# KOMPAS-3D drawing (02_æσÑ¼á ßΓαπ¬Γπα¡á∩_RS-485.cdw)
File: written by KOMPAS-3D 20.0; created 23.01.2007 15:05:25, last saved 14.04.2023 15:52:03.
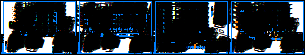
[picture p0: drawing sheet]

Sheets 1-4: A2, landscape

Document properties: Разработал: Антошин; Проверил: Тарасов; Утвердил: Шмончев; Н. контр.: Силаков; Форматы листов документа: 4xA2; Полное имя файла: \\s-tech\depts\Отдел_ПКО\Проекты\Типовые проекты МКД 2023\!Типовой проект\1_Типовой проект МКД_RS-485\02_Схема структурная_RS-485.cdw

Title block, sheet 1: Наименование: ВЛСТ 858.00.001 С3; designation: ВЛСТ 1277.01.000 С3; sheet number: 1; Количество листов документа: 8; organisation: АО ГК / "Системы и Технологии"; Форматы листов документа: A2; stored path: Y:\Проекты\ЭнергоКурган\Типовой проект\02_Рабочая док. общ\Е1_001_Сх деления.cdw; cell 302: Система учета электроэнергии (с организацией удаленного / сбора данных) потребителей; cell 303: Типовой проект ИСУЭ многоквартирного / дома с использованием проводного / канала связи RS-485; cell 304: Схема структурная АИИС; cell 320: Р
Title block, sheet 2: sheet number: 2; Форматы листов документа: A3; stored path: \\fs1.s-tech.ru\depts\Отдел_ПКО\Проекты\ГУП СК Ставрополькоммунэлектро\2021\Типовой проект\02_Рабочая документация\+С3_001_Структ_Многоквартирный дом УСПД.cdw
Title block, sheet 3: sheet number: 3
Title block, sheet 4: sheet number: 4; stored path: \\s-tech\depts\Отдел_ПКО\Проекты\Типовые проекты МКД 2023\!Типовой проект\1_Типовой проект МКД_RS-485\_Схема структурная_RS-485.cdw; designation, second copy: ВЛСТ 1277.01.000 С3-

Referenced files in \\Helios\отдел_пко\Общая папка Компас\_Addons\Signatures\: Signatures.lfr|Тарасов, Signatures.lfr, Signatures.lfr|Силаков, Signatures.lfr|Шмончев
Referenced files in C:\Program Files\ASCON\KOMPAS-3D V13\Libs\_Addons\Signatures\: Signatures.lfr
Referenced files: qlkzkl.frw, eiczbt.frw, hsklda.frw
Referenced files in C:\Program Files\ASCON\KOMPAS-3D v20\Sys\: Lighting.lts
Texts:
  Тарасов
  Силаков
  Шмончев
  Лит-Масса-Масштаб
  Материал-Предприятие
  Normal
  TXT
  Centerline
  Outline
  Этаж 2
  Этаж 1
  ВРУ №1
  Сч. ОДПУ
  Сч. МОП
  Шкаф УСПД
  УСПД
  SM-160
  Коммутатор
  Преобразователь
  Ethernet/RS-485
  RS-485
  Сч. Кв.1
  Сч. Кв.6
  Этаж 6
  ПРК
  АРК
  Электрощитовая №1
  Подвал
  Этаж 7
  Этаж 12
  Этаж 13
  Этаж 17
  Этаж 18
  Стояк СС
  Подъезд 1
  Подъезд 2
  Подъезд 3
  Подъезд N
  Электрощитовая №2
  Тех. этаж
  Вариант 3. Многоквартирный дом с этажностью - 14-18
  Щит со счетчиками на площадке этажа, активная разветвительная коробка RS-485
  GSM
  Осн. канал
  Сервер ИСУЭ
  Антенна GSM
  ВОЛС
  Оборудование
  связи
  Альт. канал
  (при необходимости)
  ВРУ №2
  ПЭФ
  Этаж 5
  Этаж 10
  Этаж 15
  ВРУ
  Сч. Кв.2
  Вариант 2. Многоквартирный дом с этажностью - 9
  Два щита со счетчиками на площадке этажа, пассивная разветвительная коробка RS-485
  Этаж 3
  Этаж 9
  Сч. Кв.3
  Сч. Кв.4
  Вариант 1. Многоквартирный дом с этажностью - до 5
  Этаж 4
  ВВГнг(А)-LS 3х2.5
  - коммутатор PLANET ISW-800T;
  интерфейса RS-485 для МКД до 18 этажей без применения АРК.
  МОП, ИПУ может изменяться.
  через ПРК ранво 30 шт. При подключении более 30 счетчиков произвести смену пары (жилы кабеля)
  магистральной линии интерфейса RS-485 (см. схема внешних проводок ВЛСТ 1277.01.002 С5).
  фаз ПЭФ-301.
  линий RS-485.
  - интеллектуальный контроллер SM160-02М/xД,
  где х - максимальное количество счетчиков (100, 150,
  - автоматический выключатель;
  Перечень сокращений
  АВ - автоматический выключатель;
  БП - блок питания;
  ВРУ - вводное распределительное устройство;
  МКД - многоквартирный дом;
  МОП -  места общего пользования;
  ОДПУ - общедомовой прибор учета;
  ПРК - пассивная разветвительная коробка;
  ПЭФ - универсальный автоматический электронный
  ИСУЭ - интеллектуальня система учета электроэнергии.
  - ПРК;
  См.ТТ п.3
  интерфейса RS-485 для МКД до 9 этажей без применения АРК.
  может изменяться.
  изменяться .
  RS-485 для МКД до 5 этажей.
  ИПУ может изменяться.
  ПЭФ-301.
  - однофазный счетчик КВАНТ ST1000-9;
  - трехфазный счетчик КВАНТ ST2000-12;
  АРК - активная разветвительная коробка;
  ПЛ - преобразователь линии;
  - АРК;
  FTP4-4х2х0,51
  - кабель FTP4-4х2х0,51.
  RS-485 для МКД до 18 этажей с применением АРК.
  Вариант 4. Многоквартирный дом с этажностью - 14-18
  Щит со счетчиками на площадке этажа, пассивная разветвительная коробка RS-485
  Сети
  сотовой
  Сети связи
  интернет
  провайдеров
  Штрих осн. черн
  POLYLINE_STYLE_0.25_RGB_0_0_0
  Питание
  Стили документа
  Разраб.
  Н.контр
  Утв.
  Многоквартирный жилой дом
  с использованием УСПД
  Структурная схема
  Антошин
  Схема структурная
  03 Рабочие чертежи основного комплекта. ГОСТ Р 21.1101-2009 Ф3
  05 Чертежи строительных изделий. Посл. листы. ГОСТ Р 21.1101-2009 Ф6
Dimensions and other numbers on the sheet: 2c5; 1c5; 3с5; 220В; 24В; 4хRS-485; 24В+RS-485; 7; 340.00.png; 8; 02.23; 1; 4; 2; 3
